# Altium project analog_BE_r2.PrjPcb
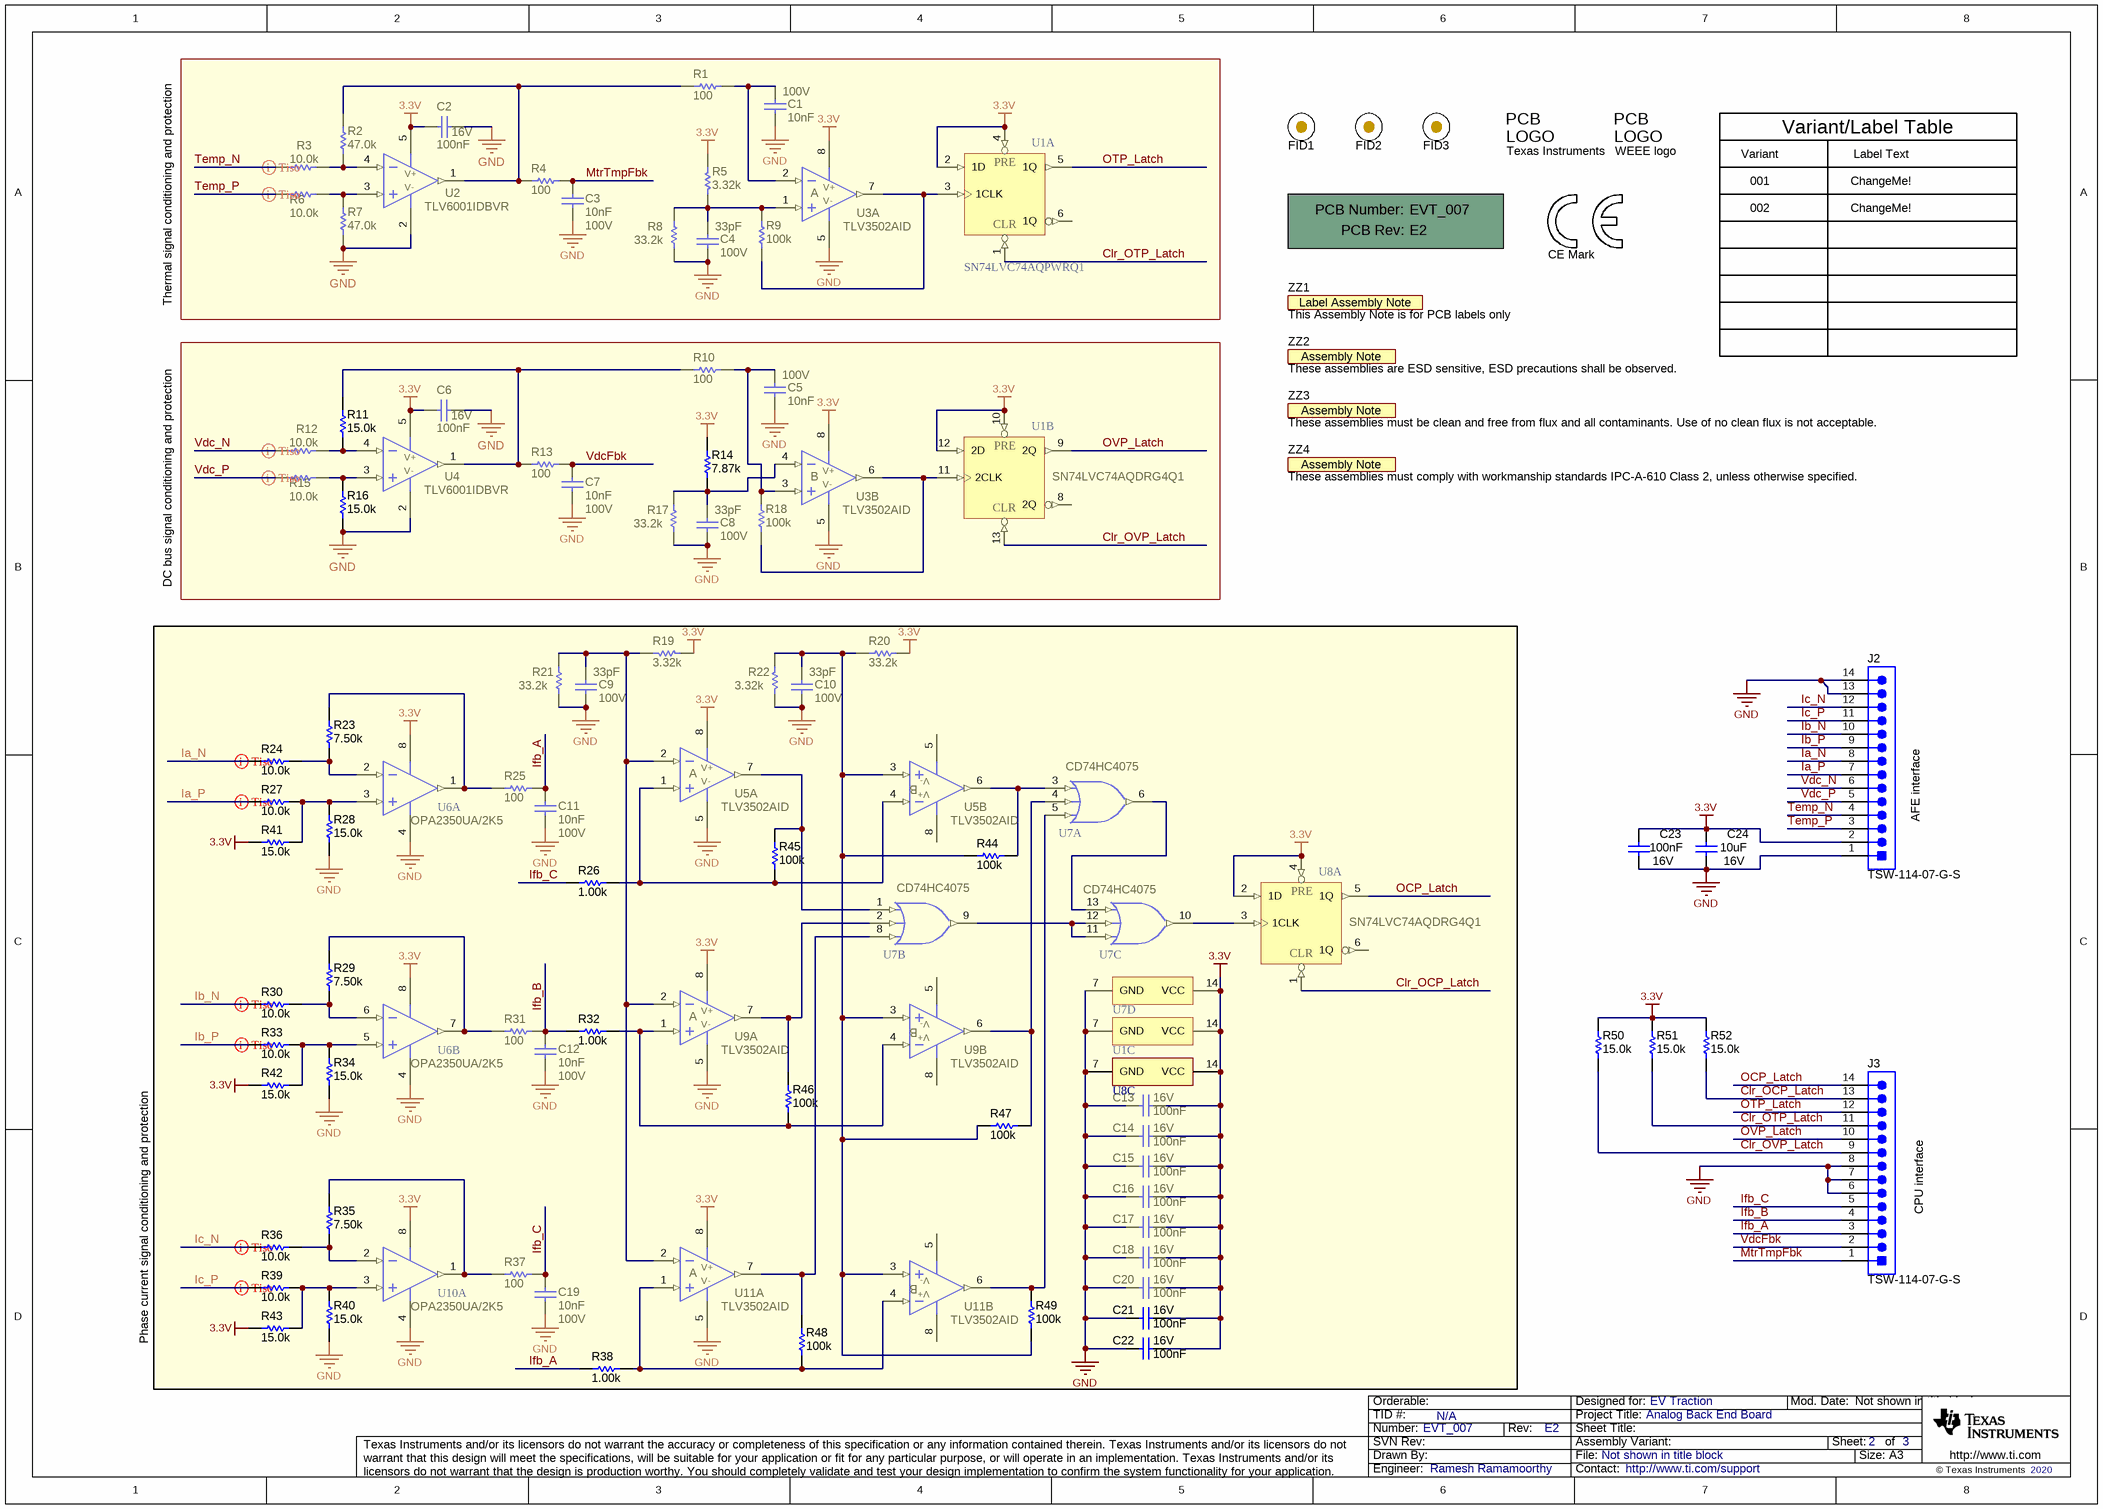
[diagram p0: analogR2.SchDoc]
CopyrightYear: 2020; PCB_Layout: Ramesh Ramamoorthy; PCB_Rev: E2; PRJ_Customer: EV Traction; PRJ_Engineer: Ramesh Ramamoorthy; PRJ_Number: EVT_007; PRJ_Title: Analog Back End Board; SCH_Rev: E2; TechSupport: http://www.ti.com/support; TID: N/A
1 sheet, 100 parts. Net scope: global (net labels, ports and power ports of the same name join across sheets).
Board file: analog_BE_R2.PcbDoc

## Sheet analogR2.SchDoc
size A3; Date: Not shown in title block; ApprovedBy: Not shown in title block; CheckedBy: Not shown in title block; Author: Not shown in title block; CompanyName: Not shown in title block; Engineer: Not shown in title block; Organization: Not shown in title block; Address1: Not shown in title block; Address2: Not shown in title block; Address3: Not shown in title block; Address4: Not shown in title block; DocumentNumber: 2; Revision: Use project parameter SCH_Rev; SheetNumber: 2; SheetTotal: 3; PageSetup: Record=PageOptions¦CenterHorizontal=True¦CenterVertical=True¦PrintScale=1.00¦XCorrection=1.00¦YCorrection=1.00¦PrintKind=0¦BorderSize=5000000¦LeftOffset=0¦BottomOffset=0¦Orientation=2¦PaperLength=1000¦PaperWidth=1000¦Scale=100¦PaperSource=15¦PrintQuality=600¦MediaType=1¦DitherType=10¦PaperKind=Letter¦PrintScaleMode=1

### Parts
!PCB1  Printed Circuit Board  (value not drawn)  (mechanical)
C1  Cap_F: 10nF  VDC_V: 100V  [0805_HV]  (hidden comment: 08051C103JAT2A)
C2  Cap_F: 100nF  VDC_V: 16V  [0805_HV]  (hidden comment: GRM219R71C104KA01D)
C3  Cap_F: 10nF  VDC_V: 100V  [0805_HV]  (hidden comment: 08051C103JAT2A)
C4  VDC_V: 100V  ValueDisplayed: 33pF  [0805_HV]  (hidden comment: 08051A330JAT2A)
C5  Cap_F: 10nF  VDC_V: 100V  [0805_HV]  (hidden comment: 08051C103JAT2A)
C6  Cap_F: 100nF  VDC_V: 16V  [0805_HV]  (hidden comment: GRM219R71C104KA01D)
C7  Cap_F: 10nF  VDC_V: 100V  [0805_HV]  (hidden comment: 08051C103JAT2A)
C8  VDC_V: 100V  ValueDisplayed: 33pF  [0805_HV]  (hidden comment: 08051A330JAT2A)
C9  VDC_V: 100V  ValueDisplayed: 33pF  [0805_HV]  (hidden comment: 08051A330JAT2A)
C10  VDC_V: 100V  ValueDisplayed: 33pF  [0805_HV]  (hidden comment: 08051A330JAT2A)
C11  Cap_F: 10nF  VDC_V: 100V  [0805_HV]  (hidden comment: 08051C103JAT2A)
C12  Cap_F: 10nF  VDC_V: 100V  [0805_HV]  (hidden comment: 08051C103JAT2A)
C13  Cap_F: 100nF  VDC_V: 16V  [0805_HV]  (hidden comment: GRM219R71C104KA01D)
C14  Cap_F: 100nF  VDC_V: 16V  [0805_HV]  (hidden comment: GRM219R71C104KA01D)
C15  Cap_F: 100nF  VDC_V: 16V  [0805_HV]  (hidden comment: GRM219R71C104KA01D)
C16  Cap_F: 100nF  VDC_V: 16V  [0805_HV]  (hidden comment: GRM219R71C104KA01D)
C17  Cap_F: 100nF  VDC_V: 16V  [0805_HV]  (hidden comment: GRM219R71C104KA01D)
C18  Cap_F: 100nF  VDC_V: 16V  [0805_HV]  (hidden comment: GRM219R71C104KA01D)
C19  Cap_F: 10nF  VDC_V: 100V  [0805_HV]  (hidden comment: 08051C103JAT2A)
C20  Cap_F: 100nF  VDC_V: 16V  [0805_HV]  (hidden comment: GRM219R71C104KA01D)
C21  Cap_F: 100nF  VDC_V: 16V  [0805_HV]  (hidden comment: GRM219R71C104KA01D)
C22  Cap_F: 100nF  VDC_V: 16V  [0805_HV]  (hidden comment: GRM219R71C104KA01D)
C23  Cap_F: 100nF  VDC_V: 16V  [0805_HV]  (hidden comment: GRM219R71C104KA01D)
C24  VDC_V: 16V  ValueDisplayed: 10uF  [0805_HV]  (hidden comment: 0805YD106MAT2A)
FID1  Fiducial  [Fiducial10-20]  (value not drawn)
FID2  Fiducial  [Fiducial10-20]  (value not drawn)
FID3  Fiducial  [Fiducial10-20]  (value not drawn)
J2  TSW-114-07-G-S  [TSW-114-07-G-S]
J3  TSW-114-07-G-S  [TSW-114-07-G-S]
Logo2  Texas Instruments  [TI_Symbol_Overlay_Small]  (no BOM)
Logo3  CE Mark  [CE_Mark_5mm]  (no BOM)
Logo4  WEEE logo  [WEEE_Minimum]  (no BOM)
R1  ValueDisplayed: 100  [0805_HV]  (hidden comment: CRCW0805100RDHEAP)
R2  ValueDisplayed: 47.0k  [0805_HV]  (hidden comment: RT0805BRD0747KL)
R3  ValueDisplayed: 10.0k  [0805_HV]  (hidden comment: RG2012P-103-B-T5)
R4  ValueDisplayed: 100  [0805_HV]  (hidden comment: CRCW0805100RDHEAP)
R5  ValueDisplayed: 3.32k  [0805_HV]  (hidden comment: RR1220P-3321-D-M)
R6  ValueDisplayed: 10.0k  [0805_HV]  (hidden comment: RG2012P-103-B-T5)
R7  ValueDisplayed: 47.0k  [0805_HV]  (hidden comment: RT0805BRD0747KL)
R8  ValueDisplayed: 33.2k  [0805_HV]  (hidden comment: RG2012P-3322-B-T5)
R9  ValueDisplayed: 100k  [0805_HV]  (hidden comment: RR1220P-104-D)
R10  ValueDisplayed: 100  [0805_HV]  (hidden comment: CRCW0805100RDHEAP)
R11  ValueDisplayed: 15.0k  [0805_HV]  (hidden comment: RT0805BRD0715KL)
R12  ValueDisplayed: 10.0k  [0805_HV]  (hidden comment: RG2012P-103-B-T5)
R13  ValueDisplayed: 100  [0805_HV]  (hidden comment: CRCW0805100RDHEAP)
R14  ValueDisplayed: 7.87k  [0805_HV]  (hidden comment: RR1220P-7871-D-M)
R15  ValueDisplayed: 10.0k  [0805_HV]  (hidden comment: RG2012P-103-B-T5)
R16  ValueDisplayed: 15.0k  [0805_HV]  (hidden comment: RT0805BRD0715KL)
R17  ValueDisplayed: 33.2k  [0805_HV]  (hidden comment: RG2012P-3322-B-T5)
R18  ValueDisplayed: 100k  [0805_HV]  (hidden comment: RR1220P-104-D)
R19  ValueDisplayed: 3.32k  [0805_HV]  (hidden comment: RR1220P-3321-D-M)
R20  ValueDisplayed: 33.2k  [0805_HV]  (hidden comment: RG2012P-3322-B-T5)
R21  ValueDisplayed: 33.2k  [0805_HV]  (hidden comment: RG2012P-3322-B-T5)
R22  ValueDisplayed: 3.32k  [0805_HV]  (hidden comment: RR1220P-3321-D-M)
R23  ValueDisplayed: 7.50k  [0805_HV]  (hidden comment: RT0805BRD077K5L)
R24  ValueDisplayed: 10.0k  [0805_HV]  (hidden comment: MCU0805MD1002BP100)
R25  ValueDisplayed: 100  [0805_HV]  (hidden comment: CRCW0805100RDHEAP)
R26  ValueDisplayed: 1.00k  [1206]  (hidden comment: CRCW12061K00FKEA)
R27  ValueDisplayed: 10.0k  [0805_HV]  (hidden comment: MCU0805MD1002BP100)
R28  ValueDisplayed: 15.0k  [0805_HV]  (hidden comment: RT0805BRD0715KL)
R29  ValueDisplayed: 7.50k  [0805_HV]  (hidden comment: RT0805BRD077K5L)
R30  ValueDisplayed: 10.0k  [0805_HV]  (hidden comment: MCU0805MD1002BP100)
R31  ValueDisplayed: 100  [0805_HV]  (hidden comment: CRCW0805100RDHEAP)
R32  ValueDisplayed: 1.00k  [1206]  (hidden comment: CRCW12061K00FKEA)
R33  ValueDisplayed: 10.0k  [0805_HV]  (hidden comment: MCU0805MD1002BP100)
R34  ValueDisplayed: 15.0k  [0805_HV]  (hidden comment: RT0805BRD0715KL)
R35  ValueDisplayed: 7.50k  [0805_HV]  (hidden comment: RT0805BRD077K5L)
R36  ValueDisplayed: 10.0k  [0805_HV]  (hidden comment: MCU0805MD1002BP100)
R37  ValueDisplayed: 100  [0805_HV]  (hidden comment: CRCW0805100RDHEAP)
R38  ValueDisplayed: 1.00k  [1206]  (hidden comment: CRCW12061K00FKEA)
R39  ValueDisplayed: 10.0k  [0805_HV]  (hidden comment: MCU0805MD1002BP100)
R40  ValueDisplayed: 15.0k  [0805_HV]  (hidden comment: RT0805BRD0715KL)
R41  ValueDisplayed: 15.0k  [0805_HV]  (hidden comment: RT0805BRD0715KL)
R42  ValueDisplayed: 15.0k  [0805_HV]  (hidden comment: RT0805BRD0715KL)
R43  ValueDisplayed: 15.0k  [0805_HV]  (hidden comment: RT0805BRD0715KL)
R44  ValueDisplayed: 100k  [0805_HV]  (hidden comment: RR1220P-104-D)
R45  ValueDisplayed: 100k  [0805_HV]  (hidden comment: RR1220P-104-D)
R46  ValueDisplayed: 100k  [0805_HV]  (hidden comment: RR1220P-104-D)
R47  ValueDisplayed: 100k  [0805_HV]  (hidden comment: RR1220P-104-D)
R48  ValueDisplayed: 100k  [0805_HV]  (hidden comment: RR1220P-104-D)
R49  ValueDisplayed: 100k  [0805_HV]  (hidden comment: RR1220P-104-D)
R50  ValueDisplayed: 15.0k  [0805_HV]  (hidden comment: RT0805BRD0715KL)
R51  ValueDisplayed: 15.0k  [0805_HV]  (hidden comment: RT0805BRD0715KL)
R52  ValueDisplayed: 15.0k  [0805_HV]  (hidden comment: RT0805BRD0715KL)
U1  SN74LVC74AQPWRQ1  [PW0014A_N]  (parts A,B,C of 3)
U2  TLV6001IDBVR  [DBV0005A_N]
U3  TLV3502AID  [D0008A_N]  (parts A,B of 2)
U4  TLV6001IDBVR  [DBV0005A_N]
U5  TLV3502AID  [D0008A_N]  (parts A,B of 2)
U6  OPA2350UA/2K5  [D0008A_N]  (parts A,B of 2)
U7  PartNumber: CD74HC4075  [D0014A_N]  (hidden comment: CD74HC4075MT)  (parts A,B,C,D of 4)
U8  PartNumber: SN74LVC74AQDRG4Q1  [PW0014A_N]  (hidden comment: SN74LVC74AQPWRQ1)  (parts A,C of 3)
U9  TLV3502AID  [D0008A_N]  (parts A,B of 2)
U10  OPA2350UA/2K5  [D0008A_N]  (part A of 2)
U11  TLV3502AID  [D0008A_N]  (parts A,B of 2)
ZZ1  This Assembly Note is for PCB labels only  [AssemblyNoteLabel]  (no BOM)
ZZ2  These assemblies are ESD sensitive, ESD precautions shall be observed.  [AssemblyNote]  (no BOM)
ZZ3  These assemblies must be clean and free from flux and all contaminants. Use of no clean flux is not acceptable.  [AssemblyNote]  (no BOM)
ZZ4  These assemblies must comply with workmanship standards IPC-A-610 Class 2, unless otherwise specified.  [AssemblyNote]  (no BOM)

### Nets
3.3V: C2.1 C6.1 C13.2 C14.2 C15.2 C16.2 C17.2 C18.2 C20.2 C21.2 C22.2 C23.2 C24.1 J2.2 R5.2 R14.2 R19.2 R20.2 R41.1 R42.1 R43.1 R50.2 R51.2 R52.2 U1.2(1D) U1.4(1~{PRE}) U1.10(2~{PRE}) U1.12(2D) U1.14(VCC) U2.5(V+) U3.8(V+) U4.5(V+) U5.8(V+) U6.8(V+) U7.14(VCC) U8.2(1D) U8.4(1~{PRE}) U8.14(VCC) U9.8(V+) U10.8(V+) U11.8(V+)
GND: C1.2 C2.2 C3.2 C4.2 C5.2 C6.2 C7.2 C8.2 C9.2 C10.2 C11.2 C12.2 C13.1 C14.1 C15.1 C16.1 C17.1 C18.1 C19.2 C20.1 C21.1 C22.1 C23.1 C24.2 J2.1 J2.13 J2.14 J3.6 J3.7 J3.8 R7.1 R8.1 R16.1 R17.1 R21.1 R22.2 R28.1 R34.1 R40.1 U1.7(GND) U2.2(V-) U3.5(V-) U4.2(V-) U5.5(V-) U6.4(V-) U7.7(GND) U8.7(GND) U9.5(V-) U10.4(V-) U11.5(V-)
Clr_OCP_Latch: J3.13 R52.1 U8.1(1~{CLR})
Clr_OTP_Latch: J3.11 R51.1 U1.1(1~{CLR})
Clr_OVP_Latch: J3.9 R50.1 U1.13(2~{CLR})
Ia_N: J2.8 R24.1
Ia_P: J2.7 R27.1
Ib_N: J2.10 R30.1
Ib_P: J2.9 R33.1
Ic_N: J2.12 R36.1
Ic_P: J2.11 R39.1
Ifb_A: C11.1 J3.3 R25.2 R38.1
Ifb_B: C12.1 J3.4 R31.2 R32.1
Ifb_C: C19.1 J3.5 R26.1 R37.2
MtrTmpFbk: C3.1 J3.1 R4.2
OCP_Latch: J3.14 U8.5(1Q)
OTP_Latch: J3.12 U1.5(1Q)
OVP_Latch: J3.10 U1.9(2Q)
Temp_N: J2.4 R3.1
Temp_P: J2.3 R6.1
Vdc_N: J2.6 R12.1
Vdc_P: J2.5 R15.1
VdcFbk: C7.1 J3.2 R13.2
NetC1_1: C1.1 R1.2 U3.2(-IN_A)
NetC4_1: C4.1 R5.1 R8.2 R9.2 U3.1(+IN_A)
NetC5_1: C5.1 R10.2 R18.2 U3.3(+IN_B)
NetC8_1: C8.1 R14.1 R17.2 U3.4(-IN_B)
NetC9_1: C9.1 R19.1 R21.2 U5.2(-IN_A) U9.2(-IN_A) U11.2(-IN_A)
NetC10_1: C10.1 R20.1 R22.1 R44.2 R47.2 R49.1 U5.3(+IN_B) U9.3(+IN_B) U11.3(+IN_B)
NetR1_1: R1.1 R2.2 R4.1 U2.1(OUT)
NetR2_1: R2.1 R3.2 U2.4(IN-)
NetR6_2: R6.2 R7.2 U2.3(IN+)
NetR9_1: R9.1 U1.3(1CLK) U3.7(OUT_A)
NetR10_1: R10.1 R11.2 R13.1 U4.1(OUT)
NetR11_1: R11.1 R12.2 U4.4(IN-)
NetR15_2: R15.2 R16.2 U4.3(IN+)
NetR18_1: R18.1 U1.11(2CLK) U3.6(OUT_B)
NetR23_1: R23.1 R24.2 U6.2(IN_A-)
NetR23_2: R23.2 R25.1 U6.1(OUT_A)
NetR26_2: R26.2 R45.1 U5.1(+IN_A) U5.4(-IN_B)
NetR27_2: R27.2 R28.2 R41.2 U6.3(IN_A+)
NetR29_1: R29.1 R30.2 U6.6(IN_B-)
NetR29_2: R29.2 R31.1 U6.7(OUT_B)
NetR32_2: R32.2 R46.1 U9.1(+IN_A) U9.4(-IN_B)
NetR33_2: R33.2 R34.2 R42.2 U6.5(IN_B+)
NetR35_1: R35.1 R36.2 U10.2(IN_A-)
NetR35_2: R35.2 R37.1 U10.1(OUT_A)
NetR38_2: R38.2 R48.1 U11.1(+IN_A) U11.4(-IN_B)
NetR39_2: R39.2 R40.2 R43.2 U10.3(IN_A+)
NetR44_1: R44.1 U5.6(OUT_B) U7.3(1A)
NetR45_2: R45.2 U5.7(OUT_A) U7.1(2A)
NetR46_2: R46.2 U7.2(2B) U9.7(OUT_A)
NetR47_1: R47.1 U7.4(1B) U9.6(OUT_B)
NetR48_2: R48.2 U7.8(2C) U11.7(OUT_A)
NetR49_2: R49.2 U7.5(1C) U11.6(OUT_B)
NetU7_6: U7.6(1Y) U7.13(3C)
NetU7_9: U7.9(2Y) U7.11(3A) U7.12(3B)
NetU7_10: U7.10(3Y) U8.3(1CLK)

Not connected (* = marked no-connect by the designer): U1 6(1Q) 8(2Q); U8 6(1Q)

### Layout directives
differential pair: Ia_N, Ia_P, Ib_N, Ib_P, Ic_N, Ic_P, Temp_N, Temp_P, Vdc_N, Vdc_P

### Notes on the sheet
- Variant
- 001
- Variant/Label Table
- Label Text
- ChangeMe!
- Thermal signal conditioning and protection
- 002
- DC bus signal conditioning and protection
- (near J2) AFE interface
- (near J3) CPU interface
- Phase current signal conditioning and protection

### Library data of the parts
!PCB1 = CMP-0003618-2: Manufacturer: Any; PartNumber: EVT_007
C1 C3 C5 C7 C11 C12 C19 = CMP-0007542-1: CAP, CERM, 0.01 uF, 100 V, +/- 5%, X7R, 0805; Manufacturer: AVX; TaMin_C: -55°C; ESR_ohm: 0.078; Polarized: N; SizeAreaWB_mm2: 6.75; Value1: 0.078 ohm; U/M: EA; Value: 0.01uF; TaMax_C: 125°C; SizeZ_mm: 1.45; SizeX_mm: 2; SizeY_mm: 1.25; Cap_Case: 0805; SizeArea_mm2: 2.5; AEC Category: Q200
C2 C6 C13-C18 C20-C23 = CMP-0008209-1: CAP, CERM, 0.1 uF, 16 V, +/- 10%, X7R, 0805; Manufacturer: MuRata; TaMin_C: -55°C; Polarized: N; SizeAreaWB_mm2: 6.75; Value1: Unknown; U/M: EA; Value: 0.1uF; TaMax_C: 125°C; SizeZ_mm: 1.45; SizeX_mm: 2; SizeY_mm: 1.25; Cap_Case: 0805; SizeArea_mm2: 2.5; AEC Category: Q200
C4 C8-C10 = CMP-0007529-1: CAP, CERM, 33 pF, 100 V, +/- 5%, C0G/NP0, 0805; Manufacturer: AVX; TaMin_C: -55°C; ESR_ohm: 0.708; Polarized: N; SizeAreaWB_mm2: 6.75; Value1: 0.708 ohm; U/M: EA; Value: 33pF; TaMax_C: 125°C; SizeZ_mm: 1.45; SizeX_mm: 2; SizeY_mm: 1.25; Cap_Case: 0805; SizeArea_mm2: 2.5; AEC Category: Q200
C24 = CMP-0007678-2: CAP, CERM, 10 uF, 16 V, +/- 20%, X5R, 0805; Manufacturer: AVX; TaMin_C: -55°C; Polarized: N; SizeAreaWB_mm2: 6.75; Value1: Unknown; U/M: EA; Value: 10uF; TaMax_C: 85°C; SizeZ_mm: 1.45; SizeX_mm: 2; SizeY_mm: 1.25; Cap_Case: 0805; SizeArea_mm2: 2.5; Cap_F: 10µF; AEC Category: Q200
FID1-FID3 = CMP-0077181-1: Fiducial mark.  There is nothing to buy or mount.
J2 J3 = CMP-0075428-1: Header, 100mil, 14x1, Gold, TH; Manufacturer: Samtec; Pitch_mm: 2.54; Cert_VDE: N; Gender: Male; Cert_CSA: Y; Voltage_V: 550V; Green_REACh: Passed; Current_A: 6.3A; CT: False; Green_Lifecycle: Active; Row_Count: 1; CNHeader: True
Logo2 = CMP-0074838-1: Texas Instrument Corporate Signature; SymbolCreator: a0412235; Lib Reference: TI_Logo; Library Reference: Logo
Logo3 = CMP-0074844-1: SymbolCreator: a0412235
Logo4 = CMP-0074769-1
R1 R4 R10 R13 R25 R31 R37 = CMP-0065350-1: RES, 100, .5%, .125 W, AEC-Q200 Grade 0, 0805; Manufacturer: Vishay-Dale; Power_W: 125mW; TempCo: 50 ppm/C; Value_Code: 100R; U/M: EA; Value: 100; EIA_Code: E192; Tolerance_%: 0.5%; SizeX_mm: 2.0; SizeY_mm: 1.25; SizeZ_mm: 1.45; Value2: .125W; SizeArea_mm2: 2.5; AEC Qualified: Y; AEC Grade: 0; AEC Category: Q200
R2 R7 = CMP-0020108-1: RES, 47.0 k, 0.1%, 0.125 W, 0805; Manufacturer: Yageo America; Power_W: 125mW; TempCo: 25 ppm/C; Value_Code: 47k0; U/M: EA; Value: 47.0k; EIA_Code: E192; Res_ohm: 47k; SizeX_mm: 2; SizeY_mm: 1.25; SizeZ_mm: 1.45; Value2: 0.125W; SizeArea_mm2: 2.5; VDC_V: 150V; AEC Category: Q200
R3 R6 R12 R15 = CMP-0018856-1: RES, 10.0 k, 0.1%, 0.125 W, 0805; Manufacturer: Susumu Co Ltd; Power_W: 125mW; TempCo: 25 ppm/C; Value_Code: 10k0; U/M: EA; Value: 10.0k; EIA_Code: E192; Res_ohm: 10k; SizeX_mm: 2; SizeY_mm: 1.25; SizeZ_mm: 1.45; Value2: 0.125W; SizeArea_mm2: 2.5; VDC_V: 100V; AEC Category: Q200
R5 R19 R22 = CMP-0019250-1: RES, 3.32 k, 0.5%, 0.1 W, 0805; Manufacturer: Susumu Co Ltd; Power_W: 100mW; TempCo: 25 ppm/C; Value_Code: 3k32; U/M: EA; Value: 3.32k; EIA_Code: E192; SizeX_mm: 2; SizeY_mm: 1.25; SizeZ_mm: 1.45; Value2: 0.1W; SizeArea_mm2: 2.5; VDC_V: 100V; AEC Category: Q200
R8 R17 R20 R21 = CMP-0018959-1: RES, 33.2 k, 0.1%, 0.125 W, 0805; Manufacturer: Susumu Co Ltd; Power_W: 125mW; TempCo: 25 ppm/C; Value_Code: 33k2; U/M: EA; Value: 33.2k; EIA_Code: E192; SizeX_mm: 2; SizeY_mm: 1.25; SizeZ_mm: 1.45; Value2: 0.125W; SizeArea_mm2: 2.5; VDC_V: 100V; AEC Category: Q200
R9 R18 R44-R49 = CMP-0019096-1: RES, 100 k, 0.5%, 0.1 W, 0805; Manufacturer: Susumu Co Ltd; Power_W: 100mW; TempCo: 25 ppm/C; U/M: EA; Value: 100k; EIA_Code: E192; SizeX_mm: 2; SizeY_mm: 1.25; SizeZ_mm: 1.45; Value2: 0.1W; SizeArea_mm2: 2.5; VDC_V: 100V; AEC Category: Q200
R11 R16 R28 R34 R40-R43 R50-R52 = CMP-0019589-2: RES, 15.0 k, 0.1%, 0.125 W, 0805; Manufacturer: Yageo America; Power_W: 125mW; TempCo: 25 ppm/C; Value_Code: 15k0; U/M: EA; Value: 15.0k; EIA_Code: E192; Res_ohm: 15k; SizeX_mm: 2; SizeY_mm: 1.25; SizeZ_mm: 1.45; Value2: 0.125W; SizeArea_mm2: 2.5; VDC_V: 150V; AEC Category: Q200
R14 = CMP-0019362-2: RES, 7.87 k, 0.5%, 0.1 W, 0805; Manufacturer: Susumu Co Ltd; Power_W: 100mW; TempCo: 25 ppm/C; Value_Code: 7k87; U/M: EA; Value: 7.87k; EIA_Code: E192; SizeX_mm: 2; SizeY_mm: 1.25; SizeZ_mm: 1.45; Value2: 0.1W; SizeArea_mm2: 2.5; VDC_V: 100V; AEC Category: Q200
R23 R29 R35 = CMP-0020336-2: RES, 7.50 k, 0.1%, 0.125 W, 0805; Manufacturer: Yageo America; Power_W: 125mW; TempCo: 25 ppm/C; Value_Code: 7k50; U/M: EA; Value: 7.50k; EIA_Code: E192; Res_ohm: 7.5k; SizeX_mm: 2; SizeY_mm: 1.25; SizeZ_mm: 1.45; Value2: 0.125W; SizeArea_mm2: 2.5; VDC_V: 150V; AEC Category: Q200
R24 R27 R30 R33 R36 R39 = CMP-0018838-2: RES, 10.0 k, 0.1%, 0.2 W, AEC-Q200 Grade 0, 0805; Manufacturer: Vishay/Beyschlag; Power_W: 200mW; TempCo: 25 ppm/C; Value_Code: 10k0; U/M: EA; Value: 10.0k; EIA_Code: E192; Res_ohm: 10k; SizeX_mm: 2; SizeY_mm: 1.25; SizeZ_mm: 1.45; Value2: 0.2W; SizeArea_mm2: 2.5; AEC Qualified: Y; VDC_V: 150V; AEC Grade: 0; AEC Category: Q200
R26 R32 R38 = CMP-0016687-3: RES, 1.00 k, 1%, 0.25 W, AEC-Q200 Grade 0, 1206; Manufacturer: Vishay-Dale; Power_W: 250mW; TempCo: 100 ppm/C; Value_Code: 1k00; Value: 1.00k; EIA_Code: E96; Res_ohm: 1k; SizeX_mm: 3.2; SizeY_mm: 1.6; SizeZ_mm: 1.35; Value2: 0.25W; SizeArea_mm2: 5.12; AEC Qualified: Y; VDC_V: 200V; AEC Category: Q200; AEC Grade: 0
U1 = CMP-0048843-1: Automotive Catalog Dual Positive-Edge-Triggered D-Type Flip-Flops With Clear And Preset, PW0014A, LARGE T&R; Generic Part Number: SN74LVC74A-Q1; Manufacturer: Texas Instruments; VCC(Min)(V): 2; Schmitt Trigger: No; Input Type: TTL,CMOS; tpd @ Nom Voltage(Max)(ns): 6,5.2; VCC(Max)(V): 3.6; Output Drive (IOL/IOH)(Max)(mA): 24/-24; F @ Nom Voltage(Max)(Mhz): 100; Technology Family: LVC; Voltage(Nom)(V): 2.7,3.3; ICC @ Nom Voltage(Max)(mA): 0.01; Output Type: LVTTL
U2 U4 = CMP-0073547-1: 1-MHz, Low-Power Operational Amplifier for Cost-Sensitive Systems, DBV0005A (SOT-23-5); Alternate PartNumber: TLV6001IDBVT; Alternate Manufacturer: Texas Instruments; SizeAreaWB_mm2: 14.82; U/M: EA; SizeZ_mm: 1.45; SizeX_mm: 2.8; SizeY_mm: 2.9; SizeArea_mm2: 8.12; CompType: IC
U3 U5 U9 U11 = CMP-0065423-1: 4.5ns Rail-to-Rail Comparator, D0008A (SOIC-8); Alternate Manufacturer: Texas Instruments; SizeAreaWB_mm2: 56.58; U/M: EA; SizeZ_mm: 1.75; SizeX_mm: 4.9; SizeY_mm: 6.2; SizeArea_mm2: 30.38; CompType: IC
U6 U10 = CMP-0040782-1: High-Speed, Single-Supply, Rail-to-Rail Operational Amplifier MicroAmplifier(TM) Series, 2.7 to 5.5 V, -40 to 85 degC, 8-pin SOIC (D8), Green (RoHS & no Sb/Br); Manufacturer: Texas Instruments; Sub Family: Low Input Bias Current Amp (<=10pA), Low Offset Voltage Amplifier (<=500uV), Low Supply Voltage Amplifier (<=2.7V), Precision Amplifier; Offset Drift(Typ)(uV/C): 4; Vn at 1kHz(Typ)(nV/rtHz): 18; Number of Channels: 2; Total Supply Voltage(Min)(+5V is 5, +/-5V is 10): 2.7; Vio (25C)(Max)(mV): 1; Iq per channel(Max)(mA): 8.5; Total Supply Voltage(Max)(+5V is 5, +/-5V is 10): 5.5; IIB(Max)(pA): 10; CMRR(Min)(dB): 74; Slew Rate(Typ)(V/us): 22
U7 = CMP-0050748-1: High Speed CMOS Logic Triple 3-Input OR Gates, D0014A, SMALL T&R; Manufacturer: Texas Instruments; VCC(Max)(V): 6; F @ Nom Voltage(Max)(Mhz): 70; VCC(Min)(V): 2; ICC @ Nom Voltage(Max)(mA): 0.02; Output Drive (IOL/IOH)(Max)(mA): 5.2/-5.2; Bits(#): 3; tpd @ Nom Voltage(Max)(ns): 25; Voltage(Nom)(V): 5; Rating: Catalog
U8 = CMP-0048843-1: Automotive Catalog Dual Positive-Edge-Triggered D-Type Flip-Flops With Clear And Preset, PW0014A, LARGE T&R; Manufacturer: Texas Instruments; VCC(Min)(V): 2; Schmitt Trigger: No; Input Type: TTL,CMOS; tpd @ Nom Voltage(Max)(ns): 6,5.2; VCC(Max)(V): 3.6; Output Drive (IOL/IOH)(Max)(mA): 24/-24; F @ Nom Voltage(Max)(Mhz): 100; Technology Family: LVC; Voltage(Nom)(V): 2.7,3.3; ICC @ Nom Voltage(Max)(mA): 0.01; Output Type: LVTTL
ZZ1 = CMP-0003616-3
ZZ2 = CMP-0077236-1
ZZ3 = CMP-0077237-1
ZZ4 = CMP-0077238-1

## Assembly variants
001: not fitted FID1 FID2 FID3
